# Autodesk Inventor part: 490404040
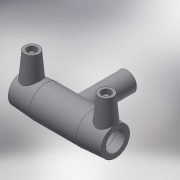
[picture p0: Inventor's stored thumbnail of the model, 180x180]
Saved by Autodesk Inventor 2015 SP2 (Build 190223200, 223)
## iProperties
Created: 2017-06
Part Number: 490404040
Material: Generic
Description: PLASSON TEE 40-40-40
Document SubType Name: Modeling
Designer: KIM
Mass: 57.3761 g
Surface Area: 241.06 cm^2
Volume: 57.3761 cm^3
Density: 1 g/cm^3
Appearance: Default
Author: KIM
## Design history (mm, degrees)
derived "490404.ipt"
feature "Solid1::490404.ipt"
tag "TaggingFeature1"
body "Solid1"
other parameters: "d2" = 56, "d3" = 43, "d5" = 50.4, "d6" = 38, "d8" = 168 deg, "d10" = 17.2, "d11" = 5.73333, "d14" = 17.6296, "d17" = 36, "d19" = 3.52592, "d20" = 168 deg, "d22" = 52.08, "d23" = 56, "d24" = 50.5176, "d25" = 135 deg, "d26" = 84, "d27" = 135 deg, "d29" = 47, "d30" = 15, "d31" = 48, "d34" = 5 deg, "d35" = 15, "d39" = 5 deg, "d40" = 9.6, "d41" = 4.8, "d42" = 6, "d43" = 0, "d45" = 4, "d46" = 14, "d47" = 0, "d51" = 0, "d52" = 32, "d54" = 0, "d55" = 50.4, "d56" = 56, "d57" = 42, "d58" = 135 deg, "d59" = 43, "d60" = 43, "d61" = 135 deg, "d72" = 54.6, "d73" = 27.3, "d75" = 42, "d77" = 0, "d78" = 32, "d80" = 0, "d82" = 62, "d83" = 0, "d84" = 3, "d85" = 0, "d86" = 3, "d87" = 0, "d88" = 12.47, "d89" = 3.1175, "d90" = 12.47, "L_1" = 43, "D_" = 56, "A_" = 47, "d_2" = 12
